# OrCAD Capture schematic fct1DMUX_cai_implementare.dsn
size B
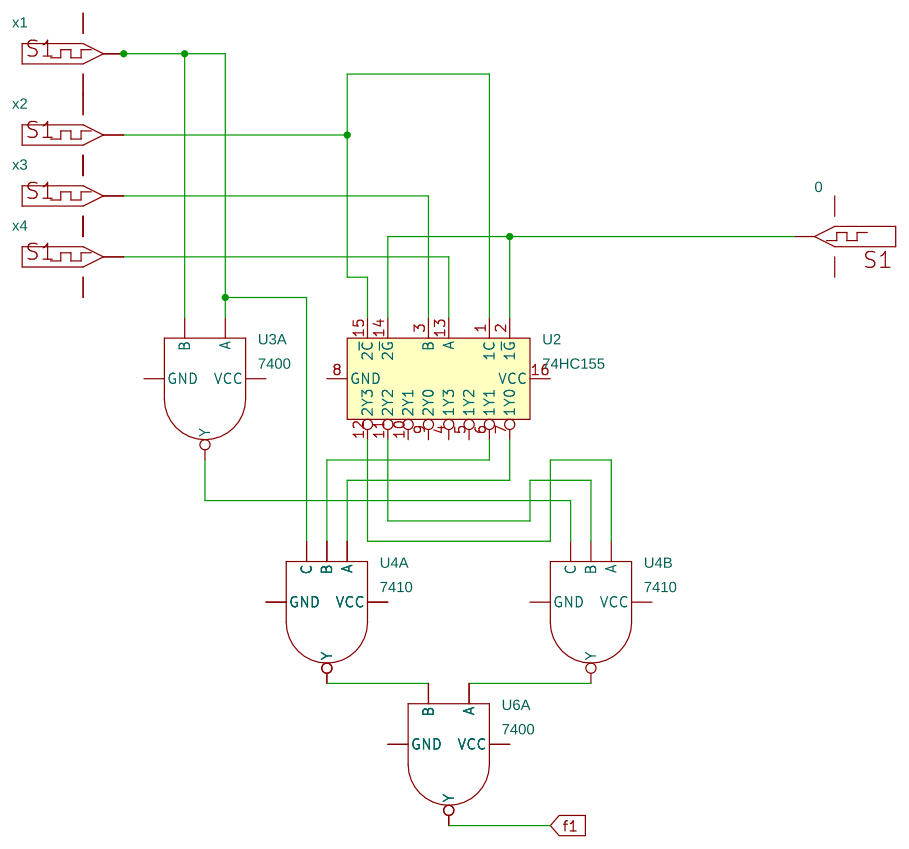
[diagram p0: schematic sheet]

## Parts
0  DigStim1
U2  74HC155  [DIP.100/16/W.300/L.900]
U3  7400  [DIP.100/14/W.300/L.800]  (section A)
U4  7410  [DIP.100/14/W.300/L.800]  (sections A,B)
U6  7400  [DIP.100/14/W.300/L.800]  (section A)
x1  DigStim1
x2  DigStim1
x3  DigStim1
x4  DigStim1

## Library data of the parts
0 x1-x4 = DigStim1
U2 = 74HC155
U3 U6 = 7400
U4 = 7410

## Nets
GND: 0.3(GND) U2.8(GND) U3.7(GND) U4.7(GND) U6.7(GND) x1.3(GND) x2.3(GND) x3.3(GND) x4.3(GND)
VCC: 0.2(VCC) U2.16(VCC) U3.14(VCC) U4.14(VCC) U6.14(VCC) x1.2(VCC) x2.2(VCC) x3.2(VCC) x4.2(VCC)
f1: U6.3(Y)
N20254: 0.OUT U2.2(1~{G}) U2.14(2~{G})
N20278: U2.13(A) x4.OUT
N20296: U2.3(B) x3.OUT
N20305: U2.1(1C) U2.15(2~{C}) x2.OUT
N20628: U3.1(A) U3.2(B) U4.13(C) x1.OUT
N20796: U2.7(1Y0) U4.1(A)
N20809: U2.6(1Y1) U4.2(B)
N20883: U3.3(Y) U4.5(C)
N20896: U2.11(2Y2) U4.4(B)
N20956: U4.12(Y) U6.2(B)
N21027: U2.12(2Y3) U4.3(A)
N21050: U4.6(Y) U6.1(A)

Not connected (* = marked no-connect by the designer): U2 4(1Y3) 5(1Y2) 9(2Y0) 10(2Y1)
